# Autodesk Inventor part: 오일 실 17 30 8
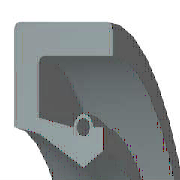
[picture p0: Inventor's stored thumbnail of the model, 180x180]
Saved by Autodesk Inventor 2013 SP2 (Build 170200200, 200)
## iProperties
IsCustomPart: 1
Created: 2012-02
Part Number: 오일 실 17 30 8
Material: 고무
Description: 오일-실
Document SubType Name: Modeling
Standard: KS B 2804
Designer: test
Standards Organization: KS
Language: ko-KR
Size Designation: S - 17 32 8
Categories: <MemberInstance><Categories><Category DisplayName="샤프트 부품" InternalName="7f7aeb1f-a693-4053-b835-cee3144e0d98" Mnemonic="SHFT"><Category DisplayName="실링" Intern
Density: 0.93 g/cm^3
Author: test
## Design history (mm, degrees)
revolve "본체" stored, may be unused: angle "d17" = 90 deg
revolve "스프링1" stored, may be unused: angle "d18" = 90 deg
body "Solid1"
sketch "스케치1"
  geometry: L1 (0, 15)-(8, 15); L2 (8, 15)-(8, 13.75); L3 (8, 13.75)-(1.75, 13.75); L4 (0, 15)-(0, 10.6); L5 (0, 10.6)-(1.75, 10.25); L6 (1.75, 10.25)-(4.9, 8.5); L7 (4.9, 8.5)-(0, 8.5); L8 (6.3, 9.375)-(6.3, 10.6); L9 (0, 0)-(9.586, 0) reference; L10 (4.9, 8.5)-(6.3, 9.375); L11 (0, 19.2)-(0, -3.2) reference; L12 (-1.917, 0)-(11.503, 0) reference; L13 (4.2, 10.6)-(1.75, 11.09); L14 (1.75, 11.09)-(1.75, 13.75); L15 (6.3, 10.6)-(5.6, 10.6); C1 r 0.455 at (4.9, 10.6); A1 r 0.7 centre (4.9, 10.6) between (5.6, 10.6) and (4.2, 10.6)
  constraints: 26 end point, 5 horizontal alignment, 4 perpendicular, 2 centre point, 2 collinear, 2 horizontal, 2 parallel, 2 point on circle, 2 point on line, 2 vertical alignment, 1 coincident
  dimensions: "d0" = 30 diameter of L1 L9 (= SD2); "d1" = 18.75 diameter of L8.start L9 (= ABDM); "d2" = 1.25 distance of L1.end L2.end (computed from SD); "d3" = 0.91 diameter of C1 (= SPDI); "d4" = 1.4 diameter of A1 (= SPDA); "d5" = 17 diameter of L6.end L9 (= NND); "d6" = 20.5 diameter of L5.end L9 (= TKDM); "d7" = 21.2 diameter of L4.end L9 (= HLDM); "d8" = 4.9 distance from line of C1.centre L4 (= SPDST); "d9" = 6.3 distance between parallel lines of L8 L4 (= SDI); "d10" = 8 distance between parallel lines of L2 L4 (= SWDT); "d12" = 1.75 distance between parallel lines of L14 L4 (= SD)
fillet "모깎기1" dims "d11" = 0.3 (= RR)
other parameters: "SD2" = 30 [user parameter; used in 1 equation term], "SWDT" = 8 [user parameter; used in 1 equation term], "RR" = 0.3 [user parameter; used in 1 equation term], "SD" = 1.75 [user parameter; used in 2 equation terms], "NND" = 17 [user parameter; used in 1 equation term], "SPDA" = 1.4 [user parameter; used in 1 equation term], "SPDI" = 0.91 [user parameter; used in 1 equation term], "TKDM" = 20.5 [user parameter; used in 1 equation term], "HLDM" = 21.2 [user parameter; used in 1 equation term], "ABDM" = 18.75 [user parameter; used in 1 equation term], "SDI" = 6.3 [user parameter; used in 1 equation term], "SPDST" = 4.9 [user parameter; used in 1 equation term], "d13" = 0, "d14" = 0, "d15" = 0, "LAB" = 0.35 [user parameter]
